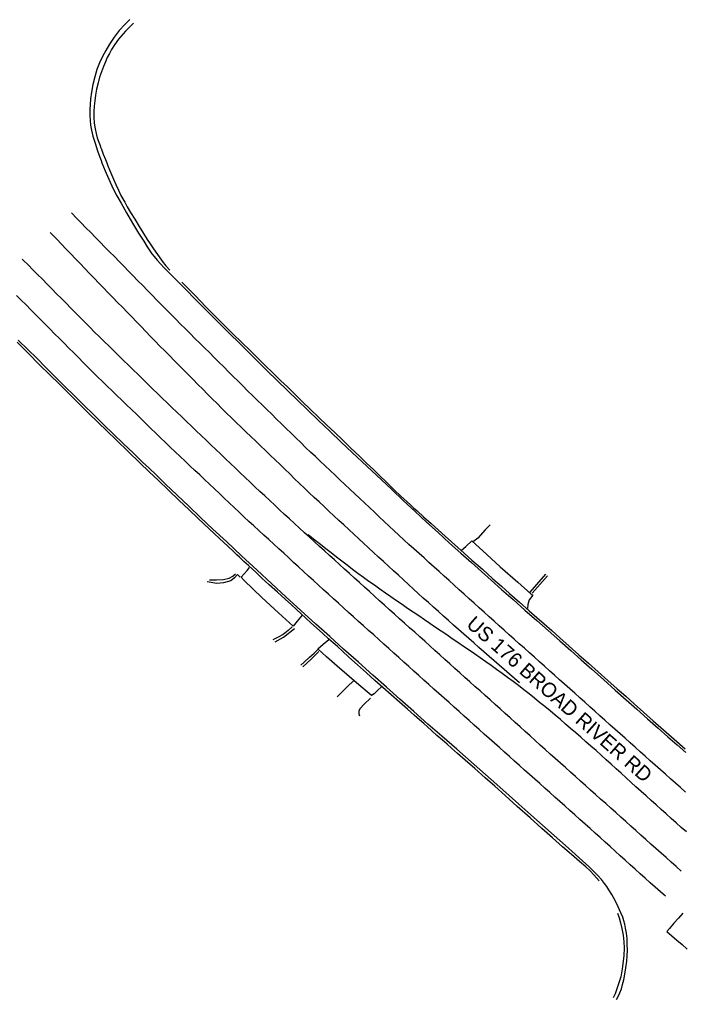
# Model space of a CAD drawing. Extents: x 1970211 to 1973046, y 801032 to 804001.
# Drawn here: x 1970657.9 to 1970903.4, y 803225.4 to 803588.1 of the extents above; entities that cross this region are included whole.
import ezdxf

# ---------------------------------------------------------------- set-up
doc = ezdxf.new("R2010")
doc.units = 0
for name, color, linetype in [('RD_EX_Conc', 7, 'Continuous'), ('RD_EX_Road', 7, 'Continuous'), ('RD_EX_Road_Paint', 7, 'Continuous'), ('RD_TX_RoadID', 7, 'Continuous')]:
    doc.layers.add(name, color=color, linetype=linetype)

msp = doc.modelspace()

# ---------------------------------------------------------------- linework, layer by layer
at = {"layer": 'RD_EX_Conc'}
for points in [[(1970700.06, 803586.74), (1970697.16, 803583.83), (1970694.57, 803580.85), (1970693.06, 803578.73), (1970691.98, 803577.02), (1970691.15, 803575.5), (1970690.39, 803574), (1970689.66, 803572.41), (1970688.92, 803570.67), (1970688.21, 803568.79), (1970687.55, 803566.78), (1970686.95, 803564.65), (1970686.42, 803562.4), (1970686, 803560.16), (1970685.71, 803558.04), (1970685.52, 803556), (1970685.39, 803554.01), (1970685.39, 803551.96), (1970685.57, 803549.74), (1970685.87, 803547.63), (1970686.22, 803545.9), (1970686.66, 803544.34), (1970687.21, 803542.73), (1970687.68, 803541.46), (1970687.89, 803540.87), (1970688.18, 803540.11), (1970688.88, 803538.3), (1970689.67, 803536.31), (1970690.18, 803535.03), (1970690.63, 803533.93), (1970691.22, 803532.46), (1970691.92, 803530.77), (1970692.71, 803528.97), (1970693.58, 803527.03), (1970694.55, 803524.92), (1970695.45, 803523.02), (1970696.12, 803521.7), (1970696.82, 803520.47), (1970697.78, 803518.83), (1970699.02, 803516.74), (1970700.54, 803514.18), (1970702.16, 803511.46), (1970703.73, 803508.89), (1970705.12, 803506.68), (1970706.2, 803505.04), (1970707.21, 803503.59), (1970708.37, 803501.96), (1970709.58, 803500.27), (1970710.74, 803498.67), (1970712.08, 803496.99), (1970713.56, 803495.37)], [(1970872.51, 803269.3), (1970870.59, 803271.49), (1970869.16, 803272.98), (1970867.59, 803274.41), (1970865.24, 803276.46), (1970862.31, 803279), (1970858.98, 803281.91), (1970855.3, 803285.16), (1970851.31, 803288.7), (1970846.97, 803292.58), (1970842.23, 803296.81), (1970837.68, 803300.88), (1970833.9, 803304.26), (1970830.36, 803307.41), (1970826.52, 803310.8), (1970822.91, 803313.97), (1970820.09, 803316.46), (1970817.91, 803318.38), (1970816.21, 803319.86), (1970814.55, 803321.3), (1970812.48, 803323.11), (1970810.46, 803324.9), (1970808.93, 803326.24), (1970807.55, 803327.46), (1970805.98, 803328.87), (1970804.03, 803330.61), (1970801.51, 803332.85), (1970798.62, 803335.4), (1970795.57, 803338.11), (1970792.47, 803340.84), (1970789.48, 803343.49), (1970786.39, 803346.23), (1970783.01, 803349.27), (1970779.85, 803352.12), (1970777.46, 803354.3), (1970775.59, 803356), (1970774.03, 803357.41), (1970772.36, 803358.91), (1970770.17, 803360.88), (1970767.84, 803362.98), (1970765.78, 803364.84), (1970763.92, 803366.53), (1970762.21, 803368.08), (1970760.47, 803369.67), (1970758.54, 803371.43), (1970756.23, 803373.53), (1970753.37, 803376.13), (1970750.38, 803378.87), (1970747.66, 803381.37), (1970745.46, 803383.41), (1970744, 803384.76), (1970742.7, 803385.96), (1970740.98, 803387.54), (1970739.36, 803389.03), (1970738.37, 803389.95), (1970737.19, 803391.06), (1970735, 803393.11), (1970731.92, 803395.99), (1970728.08, 803399.6), (1970724.08, 803403.37), (1970720.53, 803406.75), (1970716.99, 803410.13), (1970713.03, 803413.92), (1970709.17, 803417.61), (1970705.9, 803420.72), (1970702.48, 803423.99), (1970698.14, 803428.19), (1970693.77, 803432.42), (1970690.25, 803435.82), (1970686.98, 803439), (1970683.32, 803442.58), (1970679.56, 803446.27), (1970676, 803449.79), (1970672.53, 803453.22), (1970669.06, 803456.65), (1970665.33, 803460.35), (1970661.1, 803464.57), (1970656.96, 803468.73)], [(1970821.56, 803391.64), (1970823.18, 803393.09), (1970825.36, 803395.12), (1970830.89, 803390.04), (1970835.84, 803385.52), (1970842.42, 803379.78), (1970847.27, 803375.48), (1970847.95, 803375.03), (1970846.67, 803373.35), (1970846.12, 803371.54), (1970846.02, 803370.14)], [(1970762.56, 803367.56), (1970760.7, 803365.4), (1970759.17, 803363.53), (1970753.73, 803368.53), (1970747.59, 803374.22), (1970741.04, 803380.45), (1970739.99, 803381.68), (1970742.16, 803384.11), (1970743.1, 803385.22)], [(1970728.22, 803380.7), (1970730.8, 803380.64), (1970733.39, 803380.83), (1970735.51, 803381.34), (1970736.89, 803382.1), (1970737.81, 803382.87)], [(1970752.54, 803357.74), (1970755.61, 803359.48), (1970759.74, 803362.7)], [(1970791.94, 803341.09), (1970790.62, 803339.89), (1970789.17, 803338.44), (1970788.27, 803337.86), (1970782.68, 803342.63), (1970775.51, 803348.7), (1970771.5, 803352.22), (1970768.39, 803355.18), (1970770.33, 803356.88), (1970772.38, 803358.6)], [(1970762.09, 803349.11), (1970763.28, 803350.23), (1970765.29, 803352.05), (1970767, 803353.6), (1970768.41, 803354.94)], [(1970781.58, 803343.34), (1970779.36, 803341.18), (1970775.45, 803337.42)], [(1970787.82, 803336.93), (1970785.47, 803334.65), (1970784.09, 803333.13), (1970783.56, 803332.18), (1970783.54, 803331.11), (1970783.8, 803330.33)], [(1970879.37, 803257.33), (1970879.95, 803255.62), (1970880.47, 803253.71), (1970880.94, 803251.57), (1970881.37, 803249.16), (1970881.68, 803246.73), (1970881.8, 803244.49), (1970881.64, 803241.46), (1970881.09, 803236.66), (1970880.54, 803233.74), (1970878.43, 803227.41), (1970877.76, 803225.95)]]:
    msp.add_lwpolyline(points, dxfattribs=at)
at = {"layer": 'RD_EX_Road'}
for points in [[(1970698.74, 803588.09), (1970696.83, 803586.24), (1970694.83, 803584.03), (1970692.92, 803581.53), (1970691.23, 803579.01), (1970689.82, 803576.71), (1970688.61, 803574.48), (1970687.5, 803572.12), (1970686.52, 803569.62), (1970685.72, 803566.92), (1970685.07, 803564.11), (1970684.52, 803561.29), (1970684.14, 803558.71), (1970683.98, 803556.65), (1970683.95, 803554.77), (1970683.94, 803552.76), (1970684.01, 803550.77), (1970684.18, 803548.98), (1970684.53, 803547.13), (1970685.08, 803544.94), (1970685.84, 803542.41), (1970686.8, 803539.54), (1970687.65, 803537.11), (1970688.08, 803535.92), (1970688.41, 803535.06), (1970688.98, 803533.61), (1970689.55, 803532.16), (1970689.91, 803531.29), (1970690.43, 803530.15), (1970691.46, 803527.9), (1970692.73, 803525.22), (1970693.97, 803522.8), (1970695.46, 803520.1), (1970697.48, 803516.57), (1970699.74, 803512.72), (1970701.95, 803509.09), (1970703.85, 803506.05), (1970705.16, 803503.96), (1970706.11, 803502.53), (1970706.9, 803501.44), (1970707.75, 803500.39), (1970708.86, 803499.07), (1970710.13, 803497.63), (1970711.45, 803496.25), (1970713.08, 803494.6), (1970715.31, 803492.35), (1970718.67, 803488.94), (1970723.71, 803483.82), (1970729.45, 803478.04), (1970734.86, 803472.64), (1970740.02, 803467.53), (1970744.97, 803462.65), (1970749.52, 803458.19), (1970753.47, 803454.36), (1970757.11, 803450.83), (1970760.77, 803447.27), (1970764.57, 803443.59), (1970768.63, 803439.71), (1970772.83, 803435.73), (1970777.05, 803431.72), (1970781.09, 803427.89), (1970784.77, 803424.42), (1970788.29, 803421.11), (1970791.88, 803417.73), (1970795.71, 803414.12), (1970799.97, 803410.12), (1970804.37, 803406), (1970808.65, 803402.04), (1970812.89, 803398.17), (1970817.16, 803394.33), (1970821.32, 803390.62), (1970825.2, 803387.14), (1970828.92, 803383.81), (1970832.59, 803380.55), (1970836.43, 803377.14), (1970840.66, 803373.38), (1970845.06, 803369.48), (1970849.4, 803365.66), (1970853.69, 803361.9), (1970857.93, 803358.18), (1970862.04, 803354.57), (1970865.93, 803351.1), (1970869.88, 803347.57), (1970874.17, 803343.75), (1970878.48, 803339.91), (1970882.51, 803336.33), (1970886.43, 803332.84), (1970890.44, 803329.29), (1970894.34, 803325.84), (1970897.97, 803322.64), (1970901.39, 803319.63), (1970904.64, 803316.74)], [(1970718.02, 803490.84), (1970722.87, 803485.91), (1970726.92, 803481.8), (1970730.36, 803478.32), (1970733.65, 803475.02), (1970736.88, 803471.82), (1970740.15, 803468.61), (1970743.26, 803465.57), (1970746.03, 803462.87), (1970748.77, 803460.19), (1970751.81, 803457.23), (1970754.71, 803454.4), (1970757.06, 803452.12), (1970759.43, 803449.82), (1970762.43, 803446.9), (1970765.67, 803443.77), (1970768.75, 803440.8), (1970771.71, 803437.96), (1970774.62, 803435.18), (1970777.56, 803432.37), (1970780.62, 803429.46), (1970783.62, 803426.6), (1970786.41, 803423.95), (1970788.97, 803421.51), (1970791.3, 803419.25), (1970793.72, 803416.91), (1970796.52, 803414.19), (1970799.21, 803411.61), (1970801.27, 803409.68), (1970802.77, 803408.31), (1970803.8, 803407.39), (1970805.1, 803406.22), (1970807.46, 803404.08), (1970810.28, 803401.54), (1970812.94, 803399.15), (1970815.47, 803396.89), (1970817.87, 803394.76), (1970820.22, 803392.68), (1970822.57, 803390.58), (1970825.43, 803388.03), (1970829.28, 803384.59), (1970833.22, 803381.08), (1970836.34, 803378.32), (1970839.36, 803375.66), (1970842.98, 803372.45), (1970846.57, 803369.28), (1970849.5, 803366.72), (1970852.17, 803364.39), (1970854.96, 803361.93), (1970858.01, 803359.24), (1970861.44, 803356.2), (1970865.05, 803352.99), (1970868.62, 803349.81), (1970872.19, 803346.63), (1970875.78, 803343.46), (1970879.24, 803340.4), (1970882.39, 803337.59), (1970885.54, 803334.78), (1970888.96, 803331.75), (1970892.6, 803328.53), (1970896.4, 803325.17), (1970900.33, 803321.69), (1970904.38, 803318.1)], [(1970879, 803225.38), (1970879.59, 803226.5), (1970880.22, 803227.83), (1970880.76, 803229.27), (1970881.23, 803230.87), (1970881.68, 803232.67), (1970882.09, 803234.72), (1970882.47, 803237.1), (1970882.77, 803239.49), (1970882.93, 803241.57), (1970882.99, 803243.58), (1970882.97, 803245.76), (1970882.86, 803247.94), (1970882.62, 803249.94), (1970882.33, 803251.7), (1970882.05, 803253.18), (1970881.71, 803254.51), (1970881.28, 803255.83), (1970880.62, 803257.44), (1970879.62, 803259.63), (1970878.42, 803262.01), (1970877.19, 803264.18), (1970876.11, 803265.96), (1970875.34, 803267.16), (1970874.53, 803268.26), (1970873.35, 803269.73), (1970872.09, 803271.19), (1970871.07, 803272.27), (1970869.99, 803273.3), (1970868.56, 803274.65), (1970866.53, 803276.52), (1970863.64, 803279.13), (1970860.05, 803282.35), (1970855.89, 803286.04), (1970851.5, 803289.94), (1970847.2, 803293.76), (1970842.76, 803297.71), (1970837.98, 803301.96), (1970832.55, 803306.77), (1970826.21, 803312.4), (1970819.82, 803318.02), (1970814.28, 803322.82), (1970809.12, 803327.29), (1970803.86, 803331.94), (1970798.69, 803336.55), (1970793.76, 803340.91), (1970788.76, 803345.35), (1970783.36, 803350.19), (1970777.91, 803355.08), (1970772.76, 803359.69), (1970767.59, 803364.34), (1970762.06, 803369.36), (1970756.49, 803374.45), (1970751.21, 803379.31), (1970745.87, 803384.26), (1970740.11, 803389.61), (1970734.47, 803394.86), (1970729.48, 803399.5), (1970724.91, 803403.78), (1970720.52, 803407.93), (1970716.23, 803412.02), (1970711.96, 803416.12), (1970708.3, 803419.64), (1970705.84, 803422.01), (1970703.47, 803424.29), (1970700.06, 803427.55), (1970696.26, 803431.2), (1970692.7, 803434.67), (1970689.15, 803438.14), (1970685.38, 803441.8), (1970681.61, 803445.49), (1970678.06, 803448.99), (1970674.58, 803452.45), (1970671.01, 803455.98), (1970667.5, 803459.44), (1970664.23, 803462.7), (1970660.95, 803465.96), (1970657.42, 803469.44)], [(1970832.12, 803401.09), (1970830.34, 803399.2), (1970827.55, 803396.18), (1970826.01, 803394.86)], [(1970739.59, 803381.68), (1970738.63, 803382.63), (1970737.51, 803381.38), (1970736.07, 803380.34), (1970733.41, 803379.61), (1970730.89, 803379.38), (1970727.36, 803379.96)], [(1970852.64, 803382.79), (1970849.31, 803379), (1970846.81, 803376.18)], [(1970853.4, 803382.12), (1970849.69, 803378.03), (1970847.73, 803375.81)], [(1970758.9, 803363.28), (1970757.36, 803361.98), (1970755.53, 803360.43), (1970753.64, 803359.45), (1970751.68, 803358.52)], [(1970768.78, 803354.19), (1970765.84, 803351.32), (1970762.74, 803348.52)]]:
    msp.add_lwpolyline(points, dxfattribs=at)
at = {"layer": 'RD_EX_Road_Paint'}
for points in [[(1970904.54, 803302.11), (1970902.67, 803303.77), (1970900.8, 803305.43), (1970898.94, 803307.09), (1970897.07, 803308.75), (1970895.2, 803310.41), (1970893.33, 803312.07), (1970891.46, 803313.73), (1970889.59, 803315.39), (1970887.73, 803317.06), (1970885.86, 803318.72), (1970884, 803320.39), (1970882.13, 803322.05), (1970880.27, 803323.72), (1970878.4, 803325.38), (1970876.54, 803327.04), (1970874.67, 803328.71), (1970872.81, 803330.37), (1970870.94, 803332.04), (1970869.08, 803333.7), (1970867.21, 803335.37), (1970865.35, 803337.03), (1970863.48, 803338.7), (1970861.62, 803340.36), (1970859.75, 803342.03), (1970857.89, 803343.69), (1970856.02, 803345.36), (1970854.16, 803347.02), (1970852.29, 803348.69), (1970850.43, 803350.35), (1970848.56, 803352.02), (1970846.7, 803353.69), (1970844.84, 803355.35), (1970842.97, 803357.02), (1970841.11, 803358.68), (1970839.24, 803360.35), (1970837.38, 803362.02), (1970835.52, 803363.68), (1970833.65, 803365.35), (1970831.79, 803367.01), (1970829.92, 803368.68), (1970828.06, 803370.34), (1970826.2, 803372.02), (1970824.35, 803373.7), (1970822.5, 803375.38), (1970820.64, 803377.05), (1970818.79, 803378.73), (1970816.94, 803380.41), (1970815.08, 803382.09), (1970813.23, 803383.77), (1970811.38, 803385.44), (1970809.52, 803387.12), (1970807.67, 803388.8), (1970805.82, 803390.48), (1970803.96, 803392.15), (1970802.11, 803393.83), (1970800.26, 803395.51), (1970798.4, 803397.19), (1970796.57, 803398.89), (1970794.75, 803400.6), (1970792.93, 803402.31), (1970791.11, 803404.03), (1970789.29, 803405.74), (1970787.47, 803407.45), (1970785.65, 803409.17), (1970783.83, 803410.88), (1970782.01, 803412.59), (1970780.19, 803414.31), (1970778.36, 803416.02), (1970776.54, 803417.73), (1970774.72, 803419.45), (1970772.9, 803421.16), (1970771.08, 803422.87), (1970769.26, 803424.59), (1970767.44, 803426.3), (1970765.62, 803428.01), (1970763.83, 803429.75), (1970762.04, 803431.5), (1970760.25, 803433.25), (1970758.46, 803434.99), (1970756.67, 803436.74), (1970754.88, 803438.49), (1970753.09, 803440.23), (1970751.3, 803441.98), (1970749.52, 803443.73), (1970747.73, 803445.47), (1970745.94, 803447.22), (1970744.15, 803448.97), (1970742.36, 803450.71), (1970740.57, 803452.46), (1970738.79, 803454.21), (1970737.02, 803455.98), (1970735.25, 803457.74), (1970733.48, 803459.51), (1970731.71, 803461.27), (1970729.94, 803463.04), (1970728.17, 803464.8), (1970726.4, 803466.57), (1970724.62, 803468.33), (1970722.85, 803470.1), (1970721.08, 803471.86), (1970719.31, 803473.63), (1970717.54, 803475.39), (1970715.77, 803477.16), (1970714.01, 803478.93), (1970712.26, 803480.71), (1970710.51, 803482.5), (1970708.76, 803484.28), (1970707, 803486.07), (1970705.25, 803487.85), (1970703.5, 803489.63), (1970701.75, 803491.42), (1970700, 803493.2), (1970698.25, 803494.98), (1970696.49, 803496.77), (1970694.74, 803498.55), (1970692.99, 803500.34), (1970691.24, 803502.12), (1970689.49, 803503.9), (1970687.74, 803505.69), (1970685.99, 803507.47), (1970684.23, 803509.25), (1970682.48, 803511.04), (1970680.73, 803512.82), (1970678.98, 803514.61), (1970677.23, 803516.39), (1970677.07, 803516.55)], [(1970843.07, 803342.55), (1970841.18, 803344.19), (1970839.3, 803345.83), (1970837.41, 803347.46), (1970835.52, 803349.1), (1970833.63, 803350.74), (1970831.75, 803352.38), (1970829.86, 803354.02), (1970827.97, 803355.66), (1970826.1, 803357.32), (1970824.23, 803358.98), (1970822.37, 803360.64), (1970820.5, 803362.31), (1970818.63, 803363.97), (1970816.76, 803365.63), (1970814.89, 803367.29), (1970813.03, 803368.95), (1970811.16, 803370.61), (1970809.29, 803372.27), (1970807.42, 803373.94), (1970805.56, 803375.6), (1970803.72, 803377.29), (1970801.87, 803378.98), (1970800.03, 803380.67), (1970798.19, 803382.37), (1970796.35, 803384.06), (1970794.51, 803385.75), (1970792.67, 803387.44), (1970790.83, 803389.14), (1970789, 803390.83), (1970787.16, 803392.53), (1970785.32, 803394.22), (1970783.48, 803395.92), (1970781.64, 803397.61), (1970779.8, 803399.3), (1970777.96, 803401), (1970776.13, 803402.69), (1970774.3, 803404.39), (1970772.48, 803406.11), (1970770.65, 803407.82), (1970768.83, 803409.53), (1970767.01, 803411.24), (1970765.19, 803412.96), (1970763.38, 803414.68), (1970761.58, 803416.42), (1970759.77, 803418.15), (1970757.97, 803419.88), (1970756.17, 803421.61), (1970754.36, 803423.34), (1970752.56, 803425.07), (1970750.75, 803426.8), (1970748.95, 803428.53), (1970747.14, 803430.26), (1970745.34, 803431.99), (1970743.54, 803433.72), (1970741.73, 803435.45), (1970739.93, 803437.18), (1970738.12, 803438.91), (1970736.32, 803440.64), (1970734.54, 803442.39), (1970732.78, 803444.17), (1970731.01, 803445.94), (1970729.25, 803447.72), (1970727.49, 803449.49), (1970725.73, 803451.27), (1970723.97, 803453.04), (1970722.21, 803454.82), (1970720.45, 803456.59), (1970718.69, 803458.37), (1970716.93, 803460.14), (1970715.16, 803461.91), (1970713.4, 803463.69), (1970711.64, 803465.46), (1970709.89, 803467.24), (1970708.15, 803469.04), (1970706.4, 803470.83), (1970704.66, 803472.62), (1970702.92, 803474.42), (1970701.18, 803476.21), (1970699.44, 803478), (1970697.69, 803479.8), (1970695.95, 803481.59), (1970694.21, 803483.38), (1970692.47, 803485.17), (1970690.73, 803486.97), (1970688.98, 803488.76), (1970687.24, 803490.55), (1970685.5, 803492.35), (1970683.76, 803494.14), (1970682.03, 803495.95), (1970680.3, 803497.75), (1970678.57, 803499.56), (1970676.84, 803501.36), (1970675.11, 803503.17), (1970673.39, 803504.98), (1970671.66, 803506.78), (1970669.93, 803508.59), (1970669.22, 803509.33)], [(1970902.93, 803272.89), (1970901.06, 803274.55), (1970899.19, 803276.21), (1970897.32, 803277.87), (1970895.45, 803279.53), (1970893.58, 803281.19), (1970891.71, 803282.85), (1970889.85, 803284.52), (1970887.99, 803286.19), (1970886.13, 803287.86), (1970884.26, 803289.53), (1970882.4, 803291.19), (1970880.54, 803292.86), (1970878.68, 803294.53), (1970876.81, 803296.2), (1970874.95, 803297.86), (1970873.08, 803299.53), (1970871.22, 803301.19), (1970869.35, 803302.85), (1970867.48, 803304.52), (1970865.62, 803306.18), (1970863.75, 803307.84), (1970861.88, 803309.51), (1970860.02, 803311.17), (1970858.16, 803312.84), (1970856.3, 803314.51), (1970854.45, 803316.19), (1970852.59, 803317.87), (1970850.74, 803319.54), (1970848.88, 803321.22), (1970847.03, 803322.89), (1970845.17, 803324.57), (1970843.32, 803326.24), (1970841.46, 803327.92), (1970839.6, 803329.58), (1970837.73, 803331.25), (1970835.87, 803332.92), (1970834.01, 803334.59), (1970832.14, 803336.25), (1970830.28, 803337.92), (1970828.42, 803339.59), (1970826.55, 803341.25), (1970824.69, 803342.92), (1970822.83, 803344.59), (1970820.96, 803346.25), (1970819.1, 803347.92), (1970817.24, 803349.59), (1970815.38, 803351.26), (1970813.52, 803352.93), (1970811.66, 803354.6), (1970809.8, 803356.27), (1970807.94, 803357.94), (1970806.08, 803359.61), (1970804.22, 803361.28), (1970802.36, 803362.96), (1970800.5, 803364.63), (1970798.64, 803366.3), (1970796.78, 803367.97), (1970794.92, 803369.64), (1970793.06, 803371.31), (1970791.21, 803372.98), (1970789.35, 803374.66), (1970787.49, 803376.33), (1970785.64, 803378.01), (1970783.78, 803379.68), (1970781.92, 803381.35), (1970780.06, 803383.03), (1970778.21, 803384.7), (1970776.35, 803386.38), (1970774.49, 803388.05), (1970772.64, 803389.72), (1970770.78, 803391.4), (1970768.92, 803393.07), (1970767.08, 803394.76), (1970765.24, 803396.45), (1970763.4, 803398.14), (1970761.56, 803399.83), (1970759.72, 803401.53), (1970757.88, 803403.22), (1970756.03, 803404.91), (1970754.2, 803406.6), (1970752.37, 803408.31), (1970750.55, 803410.03), (1970748.73, 803411.74), (1970746.9, 803413.45), (1970745.08, 803415.16), (1970743.26, 803416.87), (1970741.43, 803418.58), (1970739.61, 803420.29), (1970737.8, 803422.01), (1970735.99, 803423.74), (1970734.18, 803425.46), (1970732.37, 803427.19), (1970730.57, 803428.92), (1970728.76, 803430.64), (1970726.95, 803432.37), (1970725.14, 803434.1), (1970723.34, 803435.82), (1970721.53, 803437.55), (1970719.73, 803439.29), (1970717.94, 803441.03), (1970716.14, 803442.76), (1970714.34, 803444.5), (1970712.54, 803446.24), (1970710.74, 803447.98), (1970708.94, 803449.71), (1970707.15, 803451.45), (1970705.35, 803453.19), (1970703.55, 803454.93), (1970701.77, 803456.68), (1970699.98, 803458.43), (1970698.2, 803460.18), (1970696.41, 803461.92), (1970694.63, 803463.67), (1970692.84, 803465.42), (1970691.05, 803467.17), (1970689.27, 803468.92), (1970687.48, 803470.67), (1970685.7, 803472.42), (1970683.94, 803474.2), (1970682.18, 803475.98), (1970680.42, 803477.75), (1970678.66, 803479.53), (1970676.9, 803481.3), (1970675.14, 803483.08), (1970673.38, 803484.85), (1970671.62, 803486.63), (1970669.86, 803488.41), (1970668.1, 803490.18), (1970666.33, 803491.95), (1970664.56, 803493.72), (1970662.8, 803495.48), (1970661.03, 803497.25), (1970659.26, 803499.02), (1970658.86, 803499.42)], [(1970897.06, 803263.58), (1970895.2, 803265.24), (1970893.33, 803266.9), (1970891.46, 803268.56), (1970889.59, 803270.22), (1970887.73, 803271.88), (1970885.87, 803273.56), (1970884.01, 803275.23), (1970882.15, 803276.91), (1970880.3, 803278.58), (1970878.44, 803280.25), (1970876.58, 803281.93), (1970874.73, 803283.6), (1970872.87, 803285.28), (1970871.01, 803286.95), (1970869.16, 803288.62), (1970867.3, 803290.3), (1970865.44, 803291.97), (1970863.59, 803293.65), (1970861.72, 803295.31), (1970859.86, 803296.98), (1970857.99, 803298.64), (1970856.13, 803300.3), (1970854.26, 803301.97), (1970852.39, 803303.63), (1970850.53, 803305.29), (1970848.66, 803306.96), (1970846.79, 803308.62), (1970844.93, 803310.28), (1970843.06, 803311.95), (1970841.2, 803313.61), (1970839.33, 803315.28), (1970837.46, 803316.94), (1970835.6, 803318.6), (1970833.73, 803320.27), (1970831.86, 803321.93), (1970830, 803323.59), (1970828.14, 803325.26), (1970826.27, 803326.92), (1970824.41, 803328.59), (1970822.54, 803330.26), (1970820.68, 803331.92), (1970818.81, 803333.59), (1970816.95, 803335.25), (1970815.08, 803336.92), (1970813.22, 803338.58), (1970811.35, 803340.25), (1970809.49, 803341.91), (1970807.62, 803343.58), (1970805.76, 803345.24), (1970803.89, 803346.91), (1970802.03, 803348.57), (1970800.17, 803350.24), (1970798.31, 803351.92), (1970796.46, 803353.59), (1970794.6, 803355.27), (1970792.74, 803356.94), (1970790.89, 803358.61), (1970789.03, 803360.29), (1970787.17, 803361.96), (1970785.32, 803363.64), (1970783.46, 803365.31), (1970781.6, 803366.99), (1970779.75, 803368.66), (1970777.89, 803370.33), (1970776.03, 803372.01), (1970774.18, 803373.68), (1970772.32, 803375.36), (1970770.48, 803377.04), (1970768.63, 803378.73), (1970766.79, 803380.42), (1970764.94, 803382.1), (1970763.1, 803383.79), (1970761.25, 803385.48), (1970759.4, 803387.16), (1970757.56, 803388.85), (1970755.71, 803390.54), (1970753.87, 803392.22), (1970752.02, 803393.91), (1970750.18, 803395.6), (1970748.33, 803397.28), (1970746.49, 803398.97), (1970744.64, 803400.66), (1970742.8, 803402.34), (1970740.97, 803404.06), (1970739.16, 803405.77), (1970737.34, 803407.49), (1970735.52, 803409.21), (1970733.7, 803410.92), (1970731.89, 803412.64), (1970730.07, 803414.36), (1970728.25, 803416.07), (1970726.44, 803417.79), (1970724.62, 803419.51), (1970722.8, 803421.22), (1970720.98, 803422.94), (1970719.17, 803424.66), (1970717.35, 803426.37), (1970715.53, 803428.09), (1970713.72, 803429.81), (1970711.92, 803431.55), (1970710.12, 803433.28), (1970708.32, 803435.02), (1970706.53, 803436.76), (1970704.73, 803438.5), (1970702.93, 803440.24), (1970701.14, 803441.97), (1970699.34, 803443.71), (1970697.54, 803445.45), (1970695.74, 803447.19), (1970693.95, 803448.92), (1970692.15, 803450.66), (1970690.35, 803452.4), (1970688.56, 803454.14), (1970686.76, 803455.88), (1970684.98, 803457.63), (1970683.22, 803459.41), (1970681.45, 803461.18), (1970679.69, 803462.95), (1970677.93, 803464.72), (1970676.17, 803466.5), (1970674.4, 803468.27), (1970672.64, 803470.04), (1970670.88, 803471.82), (1970669.11, 803473.59), (1970667.35, 803475.36), (1970665.59, 803477.13), (1970663.83, 803478.91), (1970662.06, 803480.68), (1970660.3, 803482.45), (1970658.54, 803484.23), (1970656.78, 803486)], [(1970904.83, 803287.39), (1970902.97, 803289.05), (1970901.1, 803290.71), (1970899.23, 803292.37), (1970897.36, 803294.03), (1970895.49, 803295.69), (1970893.62, 803297.35), (1970891.75, 803299.01), (1970889.89, 803300.68), (1970888.04, 803302.36), (1970886.18, 803304.04), (1970884.33, 803305.72), (1970882.48, 803307.4), (1970880.63, 803309.08), (1970878.78, 803310.76), (1970876.93, 803312.44), (1970875.08, 803314.12), (1970873.23, 803315.8), (1970871.37, 803317.47), (1970869.49, 803319.11), (1970867.6, 803320.76), (1970865.72, 803322.4), (1970863.84, 803324.05), (1970861.96, 803325.69), (1970860.06, 803327.33), (1970858.16, 803328.95), (1970856.25, 803330.56), (1970854.35, 803332.18), (1970852.41, 803333.77), (1970850.48, 803335.35), (1970848.54, 803336.93), (1970846.59, 803338.5), (1970844.61, 803340.02), (1970842.62, 803341.53), (1970840.63, 803343.05), (1970838.62, 803344.54), (1970836.6, 803346.01), (1970834.58, 803347.48), (1970832.55, 803348.94), (1970830.51, 803350.38), (1970828.46, 803351.82), (1970826.42, 803353.25), (1970824.35, 803354.66), (1970822.28, 803356.07), (1970820.22, 803357.47), (1970818.15, 803358.88), (1970816.08, 803360.28), (1970814.01, 803361.69), (1970811.95, 803363.1), (1970809.88, 803364.5), (1970807.81, 803365.91), (1970805.75, 803367.32), (1970803.69, 803368.73), (1970801.62, 803370.14), (1970799.56, 803371.55), (1970797.5, 803372.97), (1970795.44, 803374.38), (1970793.39, 803375.82), (1970791.34, 803377.26), (1970789.3, 803378.69), (1970787.25, 803380.13), (1970785.21, 803381.57), (1970783.21, 803383.07), (1970781.22, 803384.58), (1970779.23, 803386.09), (1970777.24, 803387.61), (1970775.25, 803389.12), (1970773.28, 803390.66), (1970771.31, 803392.2), (1970769.34, 803393.75), (1970767.38, 803395.29), (1970765.41, 803396.84), (1970764.73, 803397.37)], [(1970903.51, 803257.31), (1970901.86, 803255.43), (1970900.22, 803253.55), (1970898.57, 803251.67), (1970897.56, 803250.52)], [(1970897.56, 803250.52), (1970899.46, 803248.9), (1970901.36, 803247.27), (1970903.26, 803245.65), (1970905.16, 803244.03)]]:
    msp.add_lwpolyline(points, dxfattribs=at)

# ---------------------------------------------------------------- texts
at = {"layer": 'RD_TX_RoadID'}
msp.add_text('US 176 BROAD RIVER RD', height=5.4, rotation=318.5939, dxfattribs=at).set_placement((1970822.99, 803363.69))

doc.saveas('drawing.dxf')
